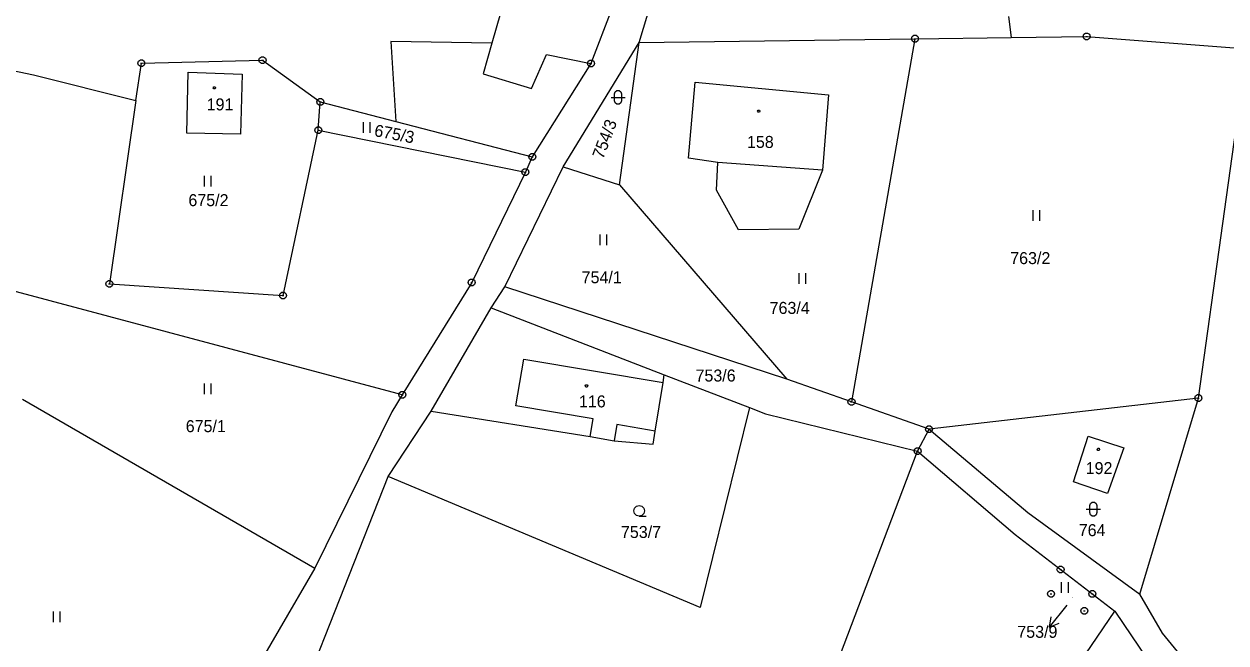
# Model space of a CAD drawing. Extents: x -694465 to -690527, y -983694 to -978978.
# Drawn here: x -691076.6 to -690906.1, y -980353.1 to -980265.4 of the extents above; entities that cross this region are included whole.
import ezdxf

# ---------------------------------------------------------------- set-up
doc = ezdxf.new("R2010")
doc.units = 0
for name, color, linetype in [('Vrstva 1', 7, 'Continuous'), ('Vrstva 16', 7, 'Continuous'), ('Vrstva 18', 7, 'Continuous'), ('Vrstva 19', 7, 'Continuous'), ('Vrstva 24', 7, 'Continuous'), ('Vrstva 25', 7, 'Continuous'), ('Vrstva 29', 7, 'Continuous')]:
    doc.layers.add(name, color=color, linetype=linetype)

msp = doc.modelspace()

# ---------------------------------------------------------------- linework, layer by layer
at = {"layer": 'Vrstva 1'}
for points in [[(-691005.12, -980250.36), (-691010.206, -980268.072)], [(-690993.19, -980263.22), (-690996.17, -980270.94)], [(-690989.33, -980267.98), (-690988.08, -980263.92)], [(-690936.98, -980264.27), (-690936.569, -980267.255)], [(-690936.569, -980267.255), (-690925.89, -980267.11)], [(-690925.89, -980267.11), (-690903.1, -980268.9)], [(-691093.56, -980268.72), (-691075.21, -980272.58)], [(-691010.206, -980268.072), (-691024.537, -980267.829)], [(-691024.537, -980267.829), (-691023.842, -980279.182)], [(-691010.206, -980268.072), (-691011.46, -980272.44)], [(-691000.1, -980285.61), (-690989.33, -980267.98)], [(-690992.13, -980288.18), (-690989.33, -980267.98)], [(-690989.33, -980267.98), (-690950.22, -980267.44)], [(-690950.22, -980267.44), (-690959.22, -980318.94)], [(-690950.22, -980267.44), (-690936.569, -980267.255)], [(-691059.91, -980270.92), (-691042.74, -980270.48)], [(-691042.74, -980270.48), (-691034.54, -980276.41)], [(-691004.61, -980274.52), (-691002.47, -980269.67)], [(-691002.47, -980269.67), (-690996.17, -980270.94)], [(-690910.02, -980318.4), (-690903.1, -980268.9)], [(-691060.7, -980276.19), (-691059.91, -980270.92)], [(-691045.61, -980272.45), (-691045.88, -980281), (-691053.47, -980280.83), (-691053.29, -980272.2), (-691045.61, -980272.45)], [(-690996.17, -980270.94), (-691004.48, -980284.2)], [(-691075.21, -980272.58), (-691060.7, -980276.19)], [(-691011.46, -980272.44), (-691004.61, -980274.52)], [(-690978.17, -980284.98), (-690982.33, -980284.37), (-690981.4, -980273.59), (-690962.46, -980275.41)], [(-690962.46, -980275.41), (-690963.31, -980286.11)], [(-691060.7, -980276.19), (-691064.44, -980302.22)], [(-691034.83, -980280.41), (-691034.54, -980276.41)], [(-691034.54, -980276.41), (-691023.842, -980279.182)], [(-691039.83, -980303.86), (-691034.83, -980280.41)], [(-691034.83, -980280.41), (-691005.47, -980286.35)], [(-691023.842, -980279.182), (-691004.48, -980284.2)], [(-691008.37, -980302.61), (-691000.1, -980285.61)], [(-691004.48, -980284.2), (-691005.47, -980286.35)], [(-691000.1, -980285.61), (-690992.13, -980288.18)], [(-690963.31, -980286.11), (-690966.69, -980294.47), (-690975.25, -980294.53), (-690978.38, -980288.9), (-690978.17, -980284.98)], [(-690963.31, -980286.11), (-690978.17, -980284.98)], [(-691005.47, -980286.35), (-691013.08, -980302)], [(-690992.13, -980288.18), (-690968.38, -980315.72)], [(-691022.92, -980317.93), (-691089.53, -980300.17)], [(-691064.44, -980302.22), (-691039.83, -980303.86)], [(-691013.08, -980302), (-691022.92, -980317.93)], [(-691010.32, -980305.63), (-691008.37, -980302.61)], [(-690968.38, -980315.72), (-691008.37, -980302.61)], [(-691018.81, -980320.25), (-691010.32, -980305.63)], [(-691010.32, -980305.63), (-690985.8, -980315.09)], [(-691006.8, -980319.52), (-691005.7, -980312.9)], [(-691005.7, -980312.9), (-690985.91, -980316.2)], [(-690987.06, -980323.08), (-690985.91, -980316.2)], [(-690985.91, -980316.2), (-690985.8, -980315.09)], [(-690985.8, -980315.09), (-690973.68, -980319.76)], [(-690959.22, -980318.94), (-690968.38, -980315.72)], [(-691022.92, -980317.93), (-691024.41, -980320.34)], [(-691076.76, -980318.55), (-691035.33, -980342.54)], [(-690995.86, -980321.35), (-691006.8, -980319.52)], [(-690973.68, -980319.76), (-690980.66, -980348.11)], [(-690973.68, -980319.76), (-690971.4, -980320.65)], [(-690948.22, -980322.82), (-690959.22, -980318.94)], [(-690910.02, -980318.4), (-690948.22, -980322.82)], [(-690918.34, -980346.2), (-690910.02, -980318.4)], [(-691024.41, -980320.34), (-691035.33, -980342.54)], [(-691024.92, -980329.53), (-691018.81, -980320.25)], [(-691018.81, -980320.25), (-690996.29, -980323.88)], [(-690996.29, -980323.88), (-690995.86, -980321.35)], [(-690971.4, -980320.65), (-690949.85, -980325.92)], [(-690992.5, -980322.18), (-690992.88, -980324.45)], [(-690987.06, -980323.08), (-690992.5, -980322.18)], [(-690987.35, -980324.93), (-690987.06, -980323.08)], [(-690949.85, -980325.92), (-690948.22, -980322.82)], [(-690948.22, -980322.82), (-690934.2, -980334.66)], [(-690996.29, -980323.88), (-690992.88, -980324.45)], [(-690992.88, -980324.45), (-690987.35, -980324.93)], [(-690920.58, -980325.47), (-690922.9, -980331.92), (-690927.76, -980330.27), (-690925.68, -980323.81), (-690920.58, -980325.47)], [(-690973.65, -980388.62), (-690949.85, -980325.92)], [(-690949.85, -980325.92), (-690936, -980337.76)], [(-691037.29, -980360.9), (-691024.92, -980329.53)], [(-690980.66, -980348.11), (-691024.92, -980329.53)], [(-690934.2, -980334.66), (-690918.34, -980346.2)], [(-690936, -980337.76), (-690921.89, -980348.64)], [(-691035.33, -980342.54), (-691045.44, -980359.93)], [(-690915.13, -980351.76), (-690918.34, -980346.2)], [(-690941.02, -980376.81), (-690921.89, -980348.64)], [(-690921.89, -980348.64), (-690917.25, -980355.49)], [(-690903.46, -980366.04), (-690915.13, -980351.76)]]:
    msp.add_lwpolyline(points, dxfattribs=at)
at = {"layer": 'Vrstva 24'}
for points in [[(-690950.066, -980266.964), (-690949.816, -980267.146), (-690949.72, -980267.44), (-690949.816, -980267.734), (-690950.066, -980267.916), (-690950.374, -980267.916), (-690950.624, -980267.734), (-690950.72, -980267.44), (-690950.624, -980267.146), (-690950.374, -980266.964)], [(-690925.736, -980266.634), (-690925.486, -980266.816), (-690925.39, -980267.11), (-690925.486, -980267.404), (-690925.736, -980267.586), (-690926.044, -980267.586), (-690926.294, -980267.404), (-690926.39, -980267.11), (-690926.294, -980266.816), (-690926.044, -980266.634)], [(-691059.756, -980270.444), (-691059.506, -980270.626), (-691059.41, -980270.92), (-691059.506, -980271.214), (-691059.756, -980271.396), (-691060.064, -980271.396), (-691060.314, -980271.214), (-691060.41, -980270.92), (-691060.314, -980270.626), (-691060.064, -980270.444)], [(-691042.586, -980270.004), (-691042.336, -980270.186), (-691042.24, -980270.48), (-691042.336, -980270.774), (-691042.586, -980270.956), (-691042.894, -980270.956), (-691043.144, -980270.774), (-691043.24, -980270.48), (-691043.144, -980270.186), (-691042.894, -980270.004)], [(-690996.016, -980270.464), (-690995.766, -980270.646), (-690995.67, -980270.94), (-690995.766, -980271.234), (-690996.016, -980271.416), (-690996.324, -980271.416), (-690996.574, -980271.234), (-690996.67, -980270.94), (-690996.574, -980270.646), (-690996.324, -980270.464)], [(-691034.386, -980275.934), (-691034.136, -980276.116), (-691034.04, -980276.41), (-691034.136, -980276.704), (-691034.386, -980276.886), (-691034.694, -980276.886), (-691034.944, -980276.704), (-691035.04, -980276.41), (-691034.944, -980276.116), (-691034.694, -980275.934)], [(-691034.676, -980279.934), (-691034.426, -980280.116), (-691034.33, -980280.41), (-691034.426, -980280.704), (-691034.676, -980280.886), (-691034.984, -980280.886), (-691035.234, -980280.704), (-691035.33, -980280.41), (-691035.234, -980280.116), (-691034.984, -980279.934)], [(-691004.326, -980283.724), (-691004.076, -980283.906), (-691003.98, -980284.2), (-691004.076, -980284.494), (-691004.326, -980284.676), (-691004.634, -980284.676), (-691004.884, -980284.494), (-691004.98, -980284.2), (-691004.884, -980283.906), (-691004.634, -980283.724)], [(-691005.316, -980285.874), (-691005.066, -980286.056), (-691004.97, -980286.35), (-691005.066, -980286.644), (-691005.316, -980286.826), (-691005.624, -980286.826), (-691005.874, -980286.644), (-691005.97, -980286.35), (-691005.874, -980286.056), (-691005.624, -980285.874)], [(-691064.286, -980301.744), (-691064.036, -980301.926), (-691063.94, -980302.22), (-691064.036, -980302.514), (-691064.286, -980302.696), (-691064.594, -980302.696), (-691064.844, -980302.514), (-691064.94, -980302.22), (-691064.844, -980301.926), (-691064.594, -980301.744)], [(-691012.926, -980301.524), (-691012.676, -980301.706), (-691012.58, -980302), (-691012.676, -980302.294), (-691012.926, -980302.476), (-691013.234, -980302.476), (-691013.484, -980302.294), (-691013.58, -980302), (-691013.484, -980301.706), (-691013.234, -980301.524)], [(-691039.676, -980303.384), (-691039.426, -980303.566), (-691039.33, -980303.86), (-691039.426, -980304.154), (-691039.676, -980304.336), (-691039.984, -980304.336), (-691040.234, -980304.154), (-691040.33, -980303.86), (-691040.234, -980303.566), (-691039.984, -980303.384)], [(-691022.766, -980317.454), (-691022.516, -980317.636), (-691022.42, -980317.93), (-691022.516, -980318.224), (-691022.766, -980318.406), (-691023.074, -980318.406), (-691023.324, -980318.224), (-691023.42, -980317.93), (-691023.324, -980317.636), (-691023.074, -980317.454)], [(-690909.866, -980317.924), (-690909.616, -980318.106), (-690909.52, -980318.4), (-690909.616, -980318.694), (-690909.866, -980318.876), (-690910.174, -980318.876), (-690910.424, -980318.694), (-690910.52, -980318.4), (-690910.424, -980318.106), (-690910.174, -980317.924)], [(-690959.066, -980318.464), (-690958.816, -980318.646), (-690958.72, -980318.94), (-690958.816, -980319.234), (-690959.066, -980319.416), (-690959.374, -980319.416), (-690959.624, -980319.234), (-690959.72, -980318.94), (-690959.624, -980318.646), (-690959.374, -980318.464)], [(-690948.066, -980322.344), (-690947.816, -980322.526), (-690947.72, -980322.82), (-690947.816, -980323.114), (-690948.066, -980323.296), (-690948.374, -980323.296), (-690948.624, -980323.114), (-690948.72, -980322.82), (-690948.624, -980322.526), (-690948.374, -980322.344)], [(-690949.696, -980325.444), (-690949.446, -980325.626), (-690949.35, -980325.92), (-690949.446, -980326.214), (-690949.696, -980326.396), (-690950.004, -980326.396), (-690950.254, -980326.214), (-690950.35, -980325.92), (-690950.254, -980325.626), (-690950.004, -980325.444)], [(-690929.426, -980342.234), (-690929.176, -980342.416), (-690929.08, -980342.71), (-690929.176, -980343.004), (-690929.426, -980343.186), (-690929.734, -980343.186), (-690929.984, -980343.004), (-690930.08, -980342.71), (-690929.984, -980342.416), (-690929.734, -980342.234)], [(-690930.756, -980345.684), (-690930.506, -980345.866), (-690930.41, -980346.16), (-690930.506, -980346.454), (-690930.756, -980346.636), (-690931.064, -980346.636), (-690931.314, -980346.454), (-690931.41, -980346.16), (-690931.314, -980345.866), (-690931.064, -980345.684)], [(-690924.916, -980345.714), (-690924.666, -980345.896), (-690924.57, -980346.19), (-690924.666, -980346.484), (-690924.916, -980346.666), (-690925.224, -980346.666), (-690925.474, -980346.484), (-690925.57, -980346.19), (-690925.474, -980345.896), (-690925.224, -980345.714)], [(-690926.046, -980348.114), (-690925.796, -980348.296), (-690925.7, -980348.59), (-690925.796, -980348.884), (-690926.046, -980349.066), (-690926.354, -980349.066), (-690926.604, -980348.884), (-690926.7, -980348.59), (-690926.604, -980348.296), (-690926.354, -980348.114)]]:
    msp.add_lwpolyline(points, close=True, dxfattribs=at)
for points in [[(-690926.009, -980267.11), (-690925.77, -980267.11)], [(-690950.339, -980267.44), (-690950.1, -980267.44)], [(-691042.859, -980270.48), (-691042.62, -980270.48)], [(-691060.029, -980270.92), (-691059.79, -980270.92)], [(-690996.289, -980270.94), (-690996.05, -980270.94)], [(-691034.659, -980276.41), (-691034.42, -980276.41)], [(-691034.949, -980280.41), (-691034.71, -980280.41)], [(-691004.599, -980284.2), (-691004.36, -980284.2)], [(-691005.589, -980286.35), (-691005.35, -980286.35)], [(-691064.559, -980302.22), (-691064.32, -980302.22)], [(-691013.199, -980302), (-691012.96, -980302)], [(-691039.949, -980303.86), (-691039.71, -980303.86)], [(-691023.039, -980317.93), (-691022.8, -980317.93)], [(-690959.339, -980318.94), (-690959.1, -980318.94)], [(-690910.139, -980318.4), (-690909.9, -980318.4)], [(-690948.339, -980322.82), (-690948.1, -980322.82)], [(-690949.969, -980325.92), (-690949.73, -980325.92)], [(-690929.699, -980342.71), (-690929.46, -980342.71)], [(-690931.029, -980346.16), (-690930.79, -980346.16)], [(-690925.189, -980346.19), (-690924.95, -980346.19)], [(-690926.319, -980348.59), (-690926.08, -980348.59)]]:
    msp.add_lwpolyline(points, dxfattribs=at)
at = {"layer": 'Vrstva 25'}
for points in [[(-691049.473, -980274.258), (-691049.385, -980274.41), (-691049.473, -980274.562), (-691049.647, -980274.562), (-691049.735, -980274.41), (-691049.647, -980274.258)], [(-690992.82, -980275.26), (-690992.725, -980274.966), (-690992.475, -980274.784), (-690992.165, -980274.784), (-690991.915, -980274.966), (-690991.82, -980275.26), (-690991.82, -980276.26), (-690991.915, -980276.554), (-690992.165, -980276.736), (-690992.475, -980276.736), (-690992.725, -980276.554), (-690992.82, -980276.26)], [(-690972.283, -980277.578), (-690972.195, -980277.73), (-690972.283, -980277.882), (-690972.457, -980277.882), (-690972.545, -980277.73), (-690972.457, -980277.578)], [(-690996.713, -980316.538), (-690996.625, -980316.69), (-690996.713, -980316.842), (-690996.887, -980316.842), (-690996.975, -980316.69), (-690996.887, -980316.538)], [(-690924.123, -980325.528), (-690924.035, -980325.68), (-690924.123, -980325.832), (-690924.297, -980325.832), (-690924.385, -980325.68), (-690924.297, -980325.528)], [(-690925.43, -980333.66), (-690925.335, -980333.366), (-690925.085, -980333.184), (-690924.775, -980333.184), (-690924.525, -980333.366), (-690924.43, -980333.66), (-690924.43, -980334.66), (-690924.525, -980334.954), (-690924.775, -980335.136), (-690925.085, -980335.136), (-690925.335, -980334.954), (-690925.43, -980334.66)]]:
    msp.add_lwpolyline(points, close=True, dxfattribs=at)
for points in [[(-690993.32, -980275.76), (-690991.32, -980275.76)], [(-691028.46, -980279.29), (-691028.46, -980280.79)], [(-691027.46, -980280.79), (-691027.46, -980279.29)], [(-691051, -980286.89), (-691051, -980288.39)], [(-691050, -980288.39), (-691050, -980286.89)], [(-690933.49, -980291.78), (-690933.49, -980293.28)], [(-690932.49, -980293.28), (-690932.49, -980291.78)], [(-690994.89, -980295.22), (-690994.89, -980296.72)], [(-690993.89, -980296.72), (-690993.89, -980295.22)], [(-690966.71, -980300.7), (-690966.71, -980302.2)], [(-690965.71, -980302.2), (-690965.71, -980300.7)], [(-691051.03, -980316.34), (-691051.03, -980317.84)], [(-691050.03, -980317.84), (-691050.03, -980316.34)], [(-690989.33, -980335.16), (-690989.705, -980335.059), (-690989.979, -980334.785), (-690990.08, -980334.41), (-690989.979, -980334.035), (-690989.705, -980333.761), (-690989.33, -980333.66), (-690988.955, -980333.761), (-690988.681, -980334.035), (-690988.58, -980334.41), (-690988.681, -980334.785), (-690988.955, -980335.059), (-690989.33, -980335.16), (-690988.33, -980335.161)], [(-690925.93, -980334.16), (-690923.93, -980334.16)], [(-690929.47, -980344.52), (-690929.47, -980346.02)], [(-690928.47, -980346.02), (-690928.47, -980344.52)], [(-691072.43, -980348.67), (-691072.43, -980350.17)], [(-691071.43, -980350.17), (-691071.43, -980348.67)]]:
    msp.add_lwpolyline(points, dxfattribs=at)
at = {"layer": 'Vrstva 29'}
for points in [[(-690928.7, -980347.77), (-690931.186, -980350.904), (-690929.79, -980350.351)], [(-690930.966, -980349.419), (-690931.186, -980350.904)]]:
    msp.add_lwpolyline(points, dxfattribs=at)

# ---------------------------------------------------------------- texts
at = {"layer": 'Vrstva 16'}
msp.add_text('753/9', height=1.7, dxfattribs=at).set_placement((-690935.707, -980352.41))
at = {"layer": 'Vrstva 18'}
for s, rotation, p in [('754/3', 69.32789, (-690994.445, -980284.62)), ('675/3', 349.21778, (-691026.985, -980281.24))]:
    msp.add_text(s, height=1.7, rotation=rotation, dxfattribs=at).set_placement(p)
for s, height, p in [('675/2', 1.7, (-691053.244, -980291.19)), ('763/2', 1.7, (-690936.714, -980299.41)), ('754/1', 1.7, (-690997.482, -980302.12)), ('763/4', 1.7, (-690970.83, -980306.47)), ('753/6', 1.7, (-690981.337, -980316.06)), ('675/1', 1.7, (-691053.622, -980323.24)), ('753/7', 1.7, (-690991.913, -980338.25)), ('764', 1.7, (-690926.994, -980337.99)), ('753/9', 0.1, (-690928.127, -980346.78))]:
    msp.add_text(s, height=height, dxfattribs=at).set_placement(p)
at = {"layer": 'Vrstva 19'}
for s, p in [('191', (-691050.658, -980277.61)), ('158', (-690974.043, -980282.93)), ('116', (-690997.868, -980319.73)), ('192', (-690926.01, -980329.19))]:
    msp.add_text(s, height=1.7, dxfattribs=at).set_placement(p)

doc.saveas('drawing.dxf')
